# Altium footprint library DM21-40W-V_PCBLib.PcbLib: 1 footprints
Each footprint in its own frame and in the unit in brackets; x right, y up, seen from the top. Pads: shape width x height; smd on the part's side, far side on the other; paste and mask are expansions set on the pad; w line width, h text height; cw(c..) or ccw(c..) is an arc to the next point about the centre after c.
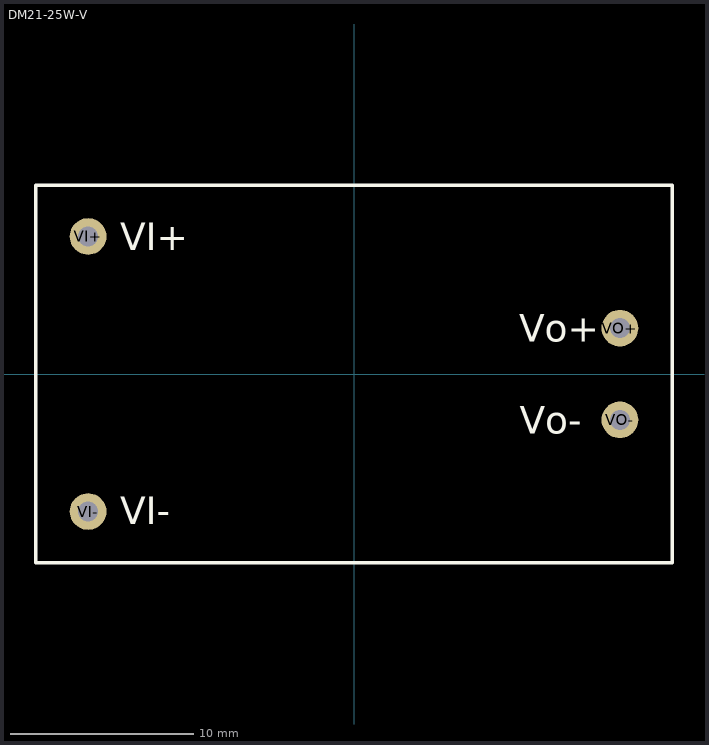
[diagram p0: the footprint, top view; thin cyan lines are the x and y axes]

## DM21-25W-V [mm]
pads (4):
  round 2 hole 1.1: VI+(-14.5,7.5) VI-(-14.5,-7.5) VO+(14.5,2.5) VO-(14.5,-2.5)
TopOverlay:
  lines w0.2: -17.35,-10.3 -17.35,10.3 17.35,10.3 17.35,-10.3 -17.35,-10.3
  text "Vo-" at 9.05,-3.25 h1.5
  text "Vo+" at 9,1.75 h1.5
  text "VI-" at -12.75,-8.2 h1.5
  text "VI+" at -12.75,6.75 h1.5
